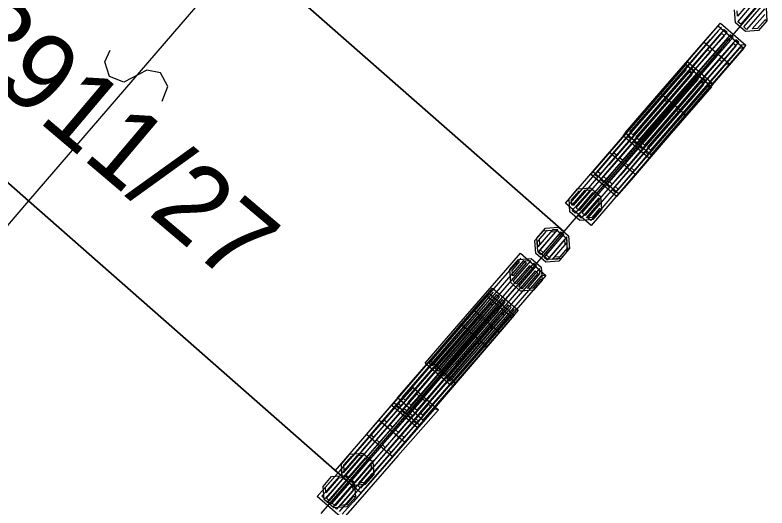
# Model space of a CAD drawing. Extents: x -266179 to -264727, y -1243225 to -1241702.
# Drawn here: x -264853.71 to -264838.18, y -1242540.46 to -1242530.28 of the extents above; entities that cross this region are included whole.
import ezdxf

# ---------------------------------------------------------------- set-up
doc = ezdxf.new("R2010")
doc.units = 0
for name, color, linetype in [('Vrstva 1', 7, 'Continuous'), ('Vrstva 19', 7, 'Continuous'), ('Vrstva 2', 7, 'Continuous'), ('Vrstva 21', 7, 'Continuous')]:
    doc.layers.add(name, color=color, linetype=linetype)

msp = doc.modelspace()

# ---------------------------------------------------------------- linework, layer by layer
at = {"layer": 'Vrstva 1'}
for p, q in [((-264853.43, -1242534.12), (-264861.06, -1242527.42)), ((-264861.06, -1242527.42), (-264853.43, -1242534.12)), ((-264842.37, -1242534.75), (-264848.98, -1242528.95)), ((-264848.98, -1242528.95), (-264842.37, -1242534.75)), ((-264838.39, -1242530.12), (-264842.37, -1242534.75)), ((-264846.83, -1242539.92), (-264853.43, -1242534.12)), ((-264853.43, -1242534.12), (-264846.83, -1242539.92)), ((-264842.37, -1242534.75), (-264842.76, -1242535.2)), ((-264842.76, -1242535.2), (-264846.83, -1242539.92)), ((-264846.83, -1242539.92), (-264847.39, -1242540.57))]:
    msp.add_line(p, q, dxfattribs=at)
at = {"layer": 'Vrstva 19'}
for p, q in [((-264838.39, -1242530.12), (-264842.37, -1242534.75)), ((-264842.37, -1242534.75), (-264842.76, -1242535.2)), ((-264842.76, -1242535.2), (-264846.83, -1242539.92)), ((-264846.83, -1242539.92), (-264847.39, -1242540.57))]:
    msp.add_line(p, q, dxfattribs=at)
for points in [[(-264838.35, -1242530.05), (-264838.717, -1242530.473), (-264838.777, -1242530.421), (-264838.41, -1242529.998)], [(-264838.523, -1242530.006), (-264838.785, -1242530.308), (-264838.793, -1242530.195)], [(-264838.229, -1242530.155), (-264838.596, -1242530.578), (-264838.656, -1242530.526), (-264838.289, -1242530.103)], [(-264838.195, -1242530.131), (-264838.176, -1242530.399), (-264838.213, -1242530.381), (-264838.37, -1242530.562), (-264838.483, -1242530.57), (-264838.221, -1242530.268)], [(-264838.176, -1242530.399), (-264838.353, -1242530.603), (-264838.621, -1242530.623), (-264838.825, -1242530.446), (-264838.844, -1242530.178)], [(-264838.61, -1242530.906), (-264839.443, -1242531.864), (-264840.276, -1242532.823), (-264840.577, -1242533.17), (-264841.106, -1242532.711), (-264840.273, -1242531.752), (-264839.44, -1242530.794), (-264839.138, -1242530.447), (-264838.61, -1242530.906), (-264838.695, -1242530.898), (-264839.528, -1242531.856), (-264840.361, -1242532.815), (-264840.584, -1242533.072), (-264840.645, -1242533.019), (-264839.812, -1242532.06), (-264838.979, -1242531.102), (-264838.756, -1242530.845), (-264838.816, -1242530.793), (-264839.649, -1242531.751), (-264840.482, -1242532.71), (-264840.705, -1242532.967), (-264840.765, -1242532.914), (-264839.932, -1242531.955), (-264839.099, -1242530.997), (-264838.876, -1242530.74), (-264838.937, -1242530.688), (-264839.77, -1242531.646), (-264840.603, -1242532.605), (-264840.826, -1242532.862), (-264840.886, -1242532.809), (-264840.053, -1242531.851), (-264839.22, -1242530.892), (-264838.997, -1242530.635), (-264839.057, -1242530.583), (-264839.89, -1242531.541), (-264840.724, -1242532.5), (-264840.947, -1242532.757), (-264841.007, -1242532.704), (-264840.174, -1242531.746), (-264839.341, -1242530.787), (-264839.118, -1242530.53)], [(-264838.654, -1242530.966), (-264839.484, -1242531.927), (-264840.314, -1242532.888), (-264840.614, -1242533.236), (-264841.144, -1242532.779), (-264840.314, -1242531.817), (-264839.484, -1242530.856), (-264839.183, -1242530.508), (-264838.654, -1242530.966), (-264838.752, -1242530.973), (-264839.582, -1242531.934), (-264840.413, -1242532.895), (-264840.635, -1242533.152), (-264840.695, -1242533.1), (-264839.865, -1242532.139), (-264839.035, -1242531.178), (-264838.813, -1242530.921), (-264838.873, -1242530.868), (-264839.703, -1242531.829), (-264840.534, -1242532.791), (-264840.756, -1242533.048), (-264840.816, -1242532.996), (-264839.986, -1242532.034), (-264839.156, -1242531.073), (-264838.934, -1242530.816), (-264838.994, -1242530.764), (-264839.825, -1242531.725), (-264840.655, -1242532.686), (-264840.877, -1242532.943), (-264840.937, -1242532.891), (-264840.107, -1242531.93), (-264839.277, -1242530.969), (-264839.055, -1242530.711), (-264839.116, -1242530.659), (-264839.946, -1242531.62), (-264840.776, -1242532.581), (-264840.998, -1242532.839), (-264841.059, -1242532.786), (-264840.228, -1242531.825), (-264839.398, -1242530.864), (-264839.176, -1242530.607)], [(-264838.944, -1242531.3), (-264839.772, -1242532.263), (-264840.6, -1242533.226), (-264840.9, -1242533.574), (-264841.431, -1242533.118), (-264840.602, -1242532.155), (-264839.774, -1242531.192), (-264839.474, -1242530.843), (-264838.944, -1242531.3), (-264839.042, -1242531.307), (-264839.87, -1242532.27), (-264840.699, -1242533.233), (-264840.92, -1242533.491), (-264840.981, -1242533.439), (-264840.153, -1242532.476), (-264839.325, -1242531.513), (-264839.103, -1242531.255), (-264839.164, -1242531.203), (-264839.992, -1242532.166), (-264840.82, -1242533.129), (-264841.042, -1242533.386), (-264841.102, -1242533.334), (-264840.274, -1242532.371), (-264839.446, -1242531.409), (-264839.224, -1242531.151), (-264839.285, -1242531.099), (-264840.113, -1242532.062), (-264840.941, -1242533.024), (-264841.163, -1242533.282), (-264841.224, -1242533.23), (-264840.395, -1242532.267), (-264839.567, -1242531.304), (-264839.345, -1242531.047), (-264839.406, -1242530.994), (-264840.234, -1242531.957), (-264841.063, -1242532.92), (-264841.284, -1242533.178), (-264841.345, -1242533.126), (-264840.517, -1242532.163), (-264839.689, -1242531.2), (-264839.467, -1242530.942)], [(-264839.329, -1242531.752), (-264840.158, -1242532.715), (-264840.986, -1242533.678), (-264841.286, -1242534.027), (-264841.816, -1242533.57), (-264840.988, -1242532.607), (-264840.16, -1242531.644), (-264839.86, -1242531.296), (-264839.329, -1242531.752), (-264839.415, -1242531.744), (-264840.243, -1242532.707), (-264841.071, -1242533.67), (-264841.293, -1242533.928), (-264841.354, -1242533.876), (-264840.526, -1242532.913), (-264839.697, -1242531.95), (-264839.476, -1242531.692), (-264839.536, -1242531.64), (-264840.365, -1242532.603), (-264841.193, -1242533.566), (-264841.415, -1242533.823), (-264841.475, -1242533.771), (-264840.647, -1242532.808), (-264839.819, -1242531.846), (-264839.597, -1242531.588), (-264839.658, -1242531.536), (-264840.486, -1242532.499), (-264841.314, -1242533.461), (-264841.536, -1242533.719), (-264841.596, -1242533.667), (-264840.768, -1242532.704), (-264839.94, -1242531.741), (-264839.718, -1242531.484), (-264839.779, -1242531.431), (-264840.607, -1242532.394), (-264841.435, -1242533.357), (-264841.657, -1242533.615), (-264841.718, -1242533.563), (-264840.89, -1242532.6), (-264840.061, -1242531.637), (-264839.84, -1242531.379)], [(-264839.32, -1242531.764), (-264840.152, -1242532.723), (-264840.984, -1242533.683), (-264841.285, -1242534.03), (-264841.814, -1242533.572), (-264840.982, -1242532.612), (-264840.15, -1242531.653), (-264839.848, -1242531.305), (-264839.32, -1242531.764), (-264839.418, -1242531.771), (-264840.25, -1242532.73), (-264841.082, -1242533.69), (-264841.305, -1242533.947), (-264841.366, -1242533.894), (-264840.534, -1242532.935), (-264839.701, -1242531.975), (-264839.479, -1242531.719), (-264839.539, -1242531.666), (-264840.371, -1242532.626), (-264841.203, -1242533.585), (-264841.426, -1242533.842), (-264841.486, -1242533.789), (-264840.654, -1242532.83), (-264839.822, -1242531.871), (-264839.6, -1242531.614), (-264839.66, -1242531.561), (-264840.492, -1242532.521), (-264841.324, -1242533.48), (-264841.547, -1242533.737), (-264841.607, -1242533.685), (-264840.775, -1242532.725), (-264839.943, -1242531.766), (-264839.72, -1242531.509), (-264839.781, -1242531.456), (-264840.613, -1242532.416), (-264841.445, -1242533.375), (-264841.668, -1242533.632), (-264841.728, -1242533.58), (-264840.896, -1242532.62), (-264840.064, -1242531.661), (-264839.841, -1242531.404)], [(-264839.284, -1242531.704), (-264840.113, -1242532.666), (-264840.943, -1242533.628), (-264841.243, -1242533.976), (-264841.773, -1242533.519), (-264840.944, -1242532.557), (-264840.115, -1242531.595), (-264839.814, -1242531.247), (-264839.284, -1242531.704), (-264839.37, -1242531.696), (-264840.199, -1242532.658), (-264841.028, -1242533.62), (-264841.25, -1242533.877), (-264841.311, -1242533.825), (-264840.482, -1242532.863), (-264839.652, -1242531.901), (-264839.431, -1242531.644), (-264839.491, -1242531.591), (-264840.32, -1242532.553), (-264841.149, -1242533.515), (-264841.371, -1242533.773), (-264841.432, -1242533.721), (-264840.603, -1242532.759), (-264839.774, -1242531.797), (-264839.552, -1242531.539), (-264839.612, -1242531.487), (-264840.441, -1242532.449), (-264841.271, -1242533.411), (-264841.493, -1242533.668), (-264841.553, -1242533.616), (-264840.724, -1242532.654), (-264839.895, -1242531.692), (-264839.673, -1242531.435), (-264839.733, -1242531.382), (-264840.563, -1242532.344), (-264841.392, -1242533.306), (-264841.614, -1242533.564), (-264841.674, -1242533.512), (-264840.845, -1242532.55), (-264840.016, -1242531.588), (-264839.794, -1242531.33)], [(-264839.846, -1242532.352), (-264840.676, -1242533.314), (-264841.505, -1242534.276), (-264841.805, -1242534.624), (-264842.335, -1242534.167), (-264841.506, -1242533.205), (-264840.677, -1242532.243), (-264840.377, -1242531.895), (-264839.846, -1242532.352), (-264839.932, -1242532.344), (-264840.761, -1242533.306), (-264841.59, -1242534.268), (-264841.812, -1242534.526), (-264841.873, -1242534.473), (-264841.044, -1242533.511), (-264840.215, -1242532.549), (-264839.993, -1242532.292), (-264840.053, -1242532.24), (-264840.882, -1242533.202), (-264841.712, -1242534.164), (-264841.934, -1242534.421), (-264841.994, -1242534.369), (-264841.165, -1242533.407), (-264840.336, -1242532.445), (-264840.114, -1242532.187), (-264840.174, -1242532.135), (-264841.004, -1242533.097), (-264841.833, -1242534.059), (-264842.055, -1242534.317), (-264842.115, -1242534.264), (-264841.286, -1242533.302), (-264840.457, -1242532.34), (-264840.235, -1242532.083), (-264840.296, -1242532.031), (-264841.125, -1242532.993), (-264841.954, -1242533.955), (-264842.176, -1242534.212), (-264842.237, -1242534.16), (-264841.407, -1242533.198), (-264840.578, -1242532.236), (-264840.356, -1242531.978)], [(-264841.597, -1242534.298), (-264841.774, -1242534.502), (-264842.042, -1242534.521), (-264842.246, -1242534.343), (-264842.265, -1242534.075), (-264842.088, -1242533.872), (-264841.82, -1242533.853), (-264841.616, -1242534.03), (-264841.597, -1242534.298), (-264841.634, -1242534.279), (-264841.791, -1242534.46), (-264841.904, -1242534.468), (-264841.642, -1242534.166), (-264841.649, -1242534.054), (-264842.017, -1242534.476), (-264842.077, -1242534.424), (-264841.71, -1242534.001), (-264841.77, -1242533.949), (-264842.138, -1242534.371), (-264842.198, -1242534.319), (-264841.831, -1242533.896), (-264841.944, -1242533.904), (-264842.206, -1242534.206), (-264842.214, -1242534.093), (-264842.056, -1242533.912)], [(-264842.3, -1242535.159), (-264842.476, -1242535.364), (-264842.744, -1242535.384), (-264842.948, -1242535.208), (-264842.969, -1242534.94), (-264842.793, -1242534.735), (-264842.525, -1242534.715), (-264842.32, -1242534.891), (-264842.3, -1242535.159), (-264842.337, -1242535.141), (-264842.493, -1242535.323), (-264842.606, -1242535.331), (-264842.345, -1242535.028), (-264842.354, -1242534.915), (-264842.719, -1242535.34), (-264842.779, -1242535.288), (-264842.414, -1242534.863), (-264842.475, -1242534.811), (-264842.84, -1242535.235), (-264842.901, -1242535.183), (-264842.536, -1242534.759), (-264842.648, -1242534.767), (-264842.909, -1242535.07), (-264842.918, -1242534.958), (-264842.761, -1242534.776)], [(-264842.258, -1242535.108), (-264842.434, -1242535.312), (-264842.702, -1242535.332), (-264842.907, -1242535.156), (-264842.927, -1242534.888), (-264842.75, -1242534.683), (-264842.482, -1242534.664), (-264842.278, -1242534.84), (-264842.258, -1242535.108), (-264842.295, -1242535.089), (-264842.452, -1242535.271), (-264842.564, -1242535.279), (-264842.303, -1242534.976), (-264842.312, -1242534.864), (-264842.677, -1242535.288), (-264842.738, -1242535.236), (-264842.372, -1242534.811), (-264842.433, -1242534.759), (-264842.798, -1242535.183), (-264842.859, -1242535.131), (-264842.493, -1242534.707), (-264842.606, -1242534.715), (-264842.867, -1242535.018), (-264842.876, -1242534.905), (-264842.719, -1242534.724)], [(-264842.742, -1242535.661), (-264843.575, -1242536.62), (-264844.408, -1242537.579), (-264844.71, -1242537.926), (-264845.238, -1242537.467), (-264844.405, -1242536.508), (-264843.572, -1242535.549), (-264843.27, -1242535.202), (-264842.742, -1242535.661), (-264842.841, -1242535.668), (-264843.674, -1242536.627), (-264844.507, -1242537.585), (-264844.73, -1242537.842), (-264844.79, -1242537.79), (-264843.957, -1242536.831), (-264843.124, -1242535.872), (-264842.901, -1242535.616), (-264842.961, -1242535.563), (-264843.794, -1242536.522), (-264844.627, -1242537.481), (-264844.85, -1242537.737), (-264844.911, -1242537.685), (-264844.078, -1242536.726), (-264843.245, -1242535.767), (-264843.022, -1242535.511), (-264843.082, -1242535.458), (-264843.915, -1242536.417), (-264844.748, -1242537.376), (-264844.971, -1242537.632), (-264845.031, -1242537.58), (-264844.198, -1242536.621), (-264843.365, -1242535.662), (-264843.142, -1242535.406), (-264843.203, -1242535.353), (-264844.036, -1242536.312), (-264844.869, -1242537.271), (-264845.092, -1242537.527), (-264845.152, -1242537.475), (-264844.319, -1242536.516), (-264843.486, -1242535.558), (-264843.263, -1242535.301)], [(-264842.82, -1242535.756), (-264842.996, -1242535.961), (-264843.264, -1242535.98), (-264843.469, -1242535.804), (-264843.489, -1242535.536), (-264843.312, -1242535.332), (-264843.045, -1242535.312), (-264842.84, -1242535.488), (-264842.82, -1242535.756), (-264842.857, -1242535.737), (-264843.014, -1242535.919), (-264843.126, -1242535.928), (-264842.865, -1242535.625), (-264842.874, -1242535.512), (-264843.239, -1242535.936), (-264843.3, -1242535.884), (-264842.934, -1242535.46), (-264842.995, -1242535.407), (-264843.36, -1242535.832), (-264843.421, -1242535.779), (-264843.055, -1242535.355), (-264843.168, -1242535.363), (-264843.429, -1242535.666), (-264843.438, -1242535.554), (-264843.281, -1242535.372)], [(-264843.397, -1242536.476), (-264844.227, -1242537.438), (-264845.056, -1242538.4), (-264845.356, -1242538.748), (-264845.886, -1242538.291), (-264845.057, -1242537.329), (-264844.228, -1242536.367), (-264843.928, -1242536.019), (-264843.397, -1242536.476), (-264843.496, -1242536.483), (-264844.325, -1242537.445), (-264845.154, -1242538.407), (-264845.376, -1242538.664), (-264845.437, -1242538.612), (-264844.608, -1242537.65), (-264843.779, -1242536.688), (-264843.557, -1242536.431), (-264843.617, -1242536.379), (-264844.447, -1242537.341), (-264845.276, -1242538.302), (-264845.498, -1242538.56), (-264845.558, -1242538.508), (-264844.729, -1242537.546), (-264843.9, -1242536.584), (-264843.678, -1242536.326), (-264843.739, -1242536.274), (-264844.568, -1242537.236), (-264845.397, -1242538.198), (-264845.619, -1242538.456), (-264845.679, -1242538.403), (-264844.85, -1242537.441), (-264844.021, -1242536.479), (-264843.799, -1242536.222), (-264843.86, -1242536.17), (-264844.689, -1242537.132), (-264845.518, -1242538.094), (-264845.74, -1242538.351), (-264845.801, -1242538.299), (-264844.971, -1242537.337), (-264844.142, -1242536.375), (-264843.92, -1242536.117)], [(-264843.316, -1242536.378), (-264844.148, -1242537.338), (-264844.98, -1242538.297), (-264845.282, -1242538.645), (-264845.81, -1242538.186), (-264844.978, -1242537.227), (-264844.146, -1242536.267), (-264843.845, -1242535.92), (-264843.316, -1242536.378), (-264843.402, -1242536.37), (-264844.234, -1242537.33), (-264845.066, -1242538.289), (-264845.289, -1242538.546), (-264845.349, -1242538.494), (-264844.517, -1242537.534), (-264843.685, -1242536.575), (-264843.462, -1242536.318), (-264843.523, -1242536.265), (-264844.355, -1242537.225), (-264845.187, -1242538.184), (-264845.41, -1242538.441), (-264845.47, -1242538.389), (-264844.638, -1242537.429), (-264843.806, -1242536.47), (-264843.583, -1242536.213), (-264843.644, -1242536.161), (-264844.476, -1242537.12), (-264845.308, -1242538.079), (-264845.53, -1242538.336), (-264845.591, -1242538.284), (-264844.759, -1242537.324), (-264843.927, -1242536.365), (-264843.704, -1242536.108), (-264843.764, -1242536.056), (-264844.596, -1242537.015), (-264845.429, -1242537.975), (-264845.651, -1242538.231), (-264845.712, -1242538.179), (-264844.88, -1242537.22), (-264844.048, -1242536.26), (-264843.825, -1242536.003)], [(-264843.438, -1242536.528), (-264844.266, -1242537.491), (-264845.094, -1242538.454), (-264845.394, -1242538.803), (-264845.925, -1242538.346), (-264845.097, -1242537.383), (-264844.268, -1242536.421), (-264843.969, -1242536.072), (-264843.438, -1242536.528), (-264843.537, -1242536.536), (-264844.365, -1242537.498), (-264845.193, -1242538.461), (-264845.415, -1242538.719), (-264845.475, -1242538.667), (-264844.647, -1242537.704), (-264843.819, -1242536.741), (-264843.597, -1242536.484), (-264843.658, -1242536.431), (-264844.486, -1242537.394), (-264845.314, -1242538.357), (-264845.536, -1242538.615), (-264845.597, -1242538.563), (-264844.768, -1242537.6), (-264843.94, -1242536.637), (-264843.718, -1242536.379), (-264843.779, -1242536.327), (-264844.607, -1242537.29), (-264845.436, -1242538.253), (-264845.657, -1242538.51), (-264845.718, -1242538.458), (-264844.89, -1242537.495), (-264844.062, -1242536.533), (-264843.84, -1242536.275), (-264843.9, -1242536.223), (-264844.729, -1242537.185), (-264845.557, -1242538.148), (-264845.779, -1242538.406), (-264845.839, -1242538.354), (-264845.011, -1242537.391), (-264844.183, -1242536.428), (-264843.961, -1242536.171)], [(-264843.704, -1242536.829), (-264844.533, -1242537.791), (-264845.362, -1242538.753), (-264845.662, -1242539.101), (-264846.193, -1242538.644), (-264845.363, -1242537.682), (-264844.534, -1242536.72), (-264844.234, -1242536.372), (-264843.704, -1242536.829), (-264843.789, -1242536.821), (-264844.619, -1242537.783), (-264845.448, -1242538.745), (-264845.67, -1242539.003), (-264845.73, -1242538.95), (-264844.901, -1242537.988), (-264844.072, -1242537.026), (-264843.85, -1242536.769), (-264843.911, -1242536.717), (-264844.74, -1242537.679), (-264845.569, -1242538.641), (-264845.791, -1242538.898), (-264845.851, -1242538.846), (-264845.022, -1242537.884), (-264844.193, -1242536.922), (-264843.971, -1242536.664), (-264844.032, -1242536.612), (-264844.861, -1242537.574), (-264845.69, -1242538.536), (-264845.912, -1242538.794), (-264845.973, -1242538.741), (-264845.143, -1242537.779), (-264844.314, -1242536.818), (-264844.092, -1242536.56), (-264844.153, -1242536.508), (-264844.982, -1242537.47), (-264845.811, -1242538.432), (-264846.033, -1242538.689), (-264846.094, -1242538.637), (-264845.265, -1242537.675), (-264844.436, -1242536.713), (-264844.214, -1242536.456)], [(-264843.96, -1242537.124), (-264844.789, -1242538.086), (-264845.618, -1242539.048), (-264845.918, -1242539.396), (-264846.448, -1242538.939), (-264845.619, -1242537.977), (-264844.79, -1242537.015), (-264844.49, -1242536.667), (-264843.96, -1242537.124), (-264844.058, -1242537.131), (-264844.887, -1242538.093), (-264845.717, -1242539.055), (-264845.939, -1242539.313), (-264845.999, -1242539.26), (-264845.17, -1242538.298), (-264844.341, -1242537.336), (-264844.119, -1242537.079), (-264844.179, -1242537.027), (-264845.009, -1242537.989), (-264845.838, -1242538.951), (-264846.06, -1242539.208), (-264846.12, -1242539.156), (-264845.291, -1242538.194), (-264844.462, -1242537.232), (-264844.24, -1242536.974), (-264844.301, -1242536.922), (-264845.13, -1242537.884), (-264845.959, -1242538.846), (-264846.181, -1242539.104), (-264846.242, -1242539.051), (-264845.412, -1242538.09), (-264844.583, -1242537.128), (-264844.361, -1242536.87), (-264844.422, -1242536.818), (-264845.251, -1242537.78), (-264846.08, -1242538.742), (-264846.302, -1242538.999), (-264846.363, -1242538.947), (-264845.534, -1242537.985), (-264844.704, -1242537.023), (-264844.482, -1242536.766)], [(-264844.604, -1242537.874), (-264845.433, -1242538.836), (-264846.262, -1242539.798), (-264846.563, -1242540.146), (-264847.093, -1242539.689), (-264846.264, -1242538.727), (-264845.435, -1242537.765), (-264845.134, -1242537.417), (-264844.604, -1242537.874), (-264844.69, -1242537.866), (-264845.519, -1242538.828), (-264846.348, -1242539.79), (-264846.57, -1242540.047), (-264846.631, -1242539.995), (-264845.802, -1242539.033), (-264844.972, -1242538.071), (-264844.75, -1242537.814), (-264844.811, -1242537.761), (-264845.64, -1242538.723), (-264846.469, -1242539.685), (-264846.691, -1242539.943), (-264846.752, -1242539.891), (-264845.923, -1242538.929), (-264845.094, -1242537.967), (-264844.872, -1242537.709), (-264844.932, -1242537.657), (-264845.761, -1242538.619), (-264846.591, -1242539.581), (-264846.813, -1242539.839), (-264846.873, -1242539.786), (-264846.044, -1242538.824), (-264845.215, -1242537.862), (-264844.993, -1242537.605), (-264845.053, -1242537.553), (-264845.883, -1242538.515), (-264846.712, -1242539.477), (-264846.934, -1242539.734), (-264846.994, -1242539.682), (-264846.165, -1242538.72), (-264845.336, -1242537.758), (-264845.114, -1242537.5)], [(-264844.962, -1242538.431), (-264845.8, -1242539.385), (-264846.638, -1242540.34), (-264846.941, -1242540.685), (-264847.467, -1242540.223), (-264846.629, -1242539.269), (-264845.792, -1242538.315), (-264845.488, -1242537.969), (-264844.962, -1242538.431), (-264845.048, -1242538.422), (-264845.886, -1242539.376), (-264846.723, -1242540.331), (-264846.948, -1242540.586)], [(-264847.008, -1242540.534), (-264846.17, -1242539.579), (-264845.332, -1242538.625), (-264845.108, -1242538.369), (-264845.168, -1242538.316), (-264846.006, -1242539.271), (-264846.844, -1242540.225), (-264847.068, -1242540.481), (-264847.128, -1242540.428), (-264846.29, -1242539.474), (-264845.452, -1242538.519), (-264845.228, -1242538.264), (-264845.288, -1242538.211), (-264846.126, -1242539.165), (-264846.964, -1242540.12), (-264847.188, -1242540.375), (-264847.248, -1242540.323), (-264846.41, -1242539.368), (-264845.573, -1242538.414), (-264845.348, -1242538.158), (-264845.408, -1242538.105), (-264846.246, -1242539.06), (-264847.084, -1242540.014), (-264847.308, -1242540.27), (-264847.368, -1242540.217), (-264846.531, -1242539.263), (-264845.693, -1242538.308), (-264845.469, -1242538.053)], [(-264846.3, -1242539.773), (-264846.477, -1242539.977), (-264846.745, -1242539.996), (-264846.949, -1242539.82), (-264846.968, -1242539.552), (-264846.791, -1242539.348), (-264846.523, -1242539.328), (-264846.319, -1242539.505), (-264846.3, -1242539.773), (-264846.337, -1242539.755), (-264846.494, -1242539.936), (-264846.607, -1242539.944), (-264846.345, -1242539.642), (-264846.353, -1242539.529), (-264846.72, -1242539.952), (-264846.78, -1242539.9), (-264846.413, -1242539.477), (-264846.474, -1242539.424), (-264846.841, -1242539.847), (-264846.901, -1242539.795), (-264846.534, -1242539.372), (-264846.647, -1242539.38), (-264846.909, -1242539.682), (-264846.917, -1242539.569), (-264846.76, -1242539.388)], [(-264846.677, -1242540.233), (-264846.854, -1242540.438), (-264847.122, -1242540.457), (-264847.326, -1242540.281), (-264847.346, -1242540.013), (-264847.17, -1242539.809), (-264846.902, -1242539.789), (-264846.697, -1242539.965), (-264846.677, -1242540.233), (-264846.714, -1242540.215), (-264846.871, -1242540.396), (-264846.984, -1242540.405), (-264846.723, -1242540.102), (-264846.731, -1242539.989), (-264847.097, -1242540.413), (-264847.157, -1242540.361), (-264846.792, -1242539.937), (-264846.852, -1242539.884), (-264847.218, -1242540.309), (-264847.278, -1242540.256), (-264846.913, -1242539.832), (-264847.026, -1242539.841), (-264847.287, -1242540.144), (-264847.295, -1242540.031), (-264847.138, -1242539.849)]]:
    msp.add_lwpolyline(points, dxfattribs=at)
at = {"layer": 'Vrstva 2'}
for p, q in [((-264848.98, -1242528.95), (-264853.43, -1242534.12)), ((-264853.43, -1242534.12), (-264858.88, -1242540.46))]:
    msp.add_line(p, q, dxfattribs=at)
msp.add_lwpolyline([(-264850.669, -1242532.062), (-264850.55, -1242531.755), (-264850.706, -1242531.476), (-264850.987, -1242531.419), (-264851.464, -1242531.668), (-264851.757, -1242531.548), (-264851.857, -1242531.251), (-264851.741, -1242531.008)], dxfattribs=at)
at = {"layer": 'Vrstva 21'}
for p, q in [((-264838.39, -1242530.12), (-264842.37, -1242534.75)), ((-264842.37, -1242534.75), (-264842.76, -1242535.2)), ((-264842.76, -1242535.2), (-264846.83, -1242539.92)), ((-264846.83, -1242539.92), (-264847.39, -1242540.57))]:
    msp.add_line(p, q, dxfattribs=at)

# ---------------------------------------------------------------- texts
at = {"layer": 'Vrstva 1'}
msp.add_text('3911/27', height=1.6, rotation=319.7677, dxfattribs=at).set_placement((-264855.074, -1242530.923))

doc.saveas('drawing.dxf')
